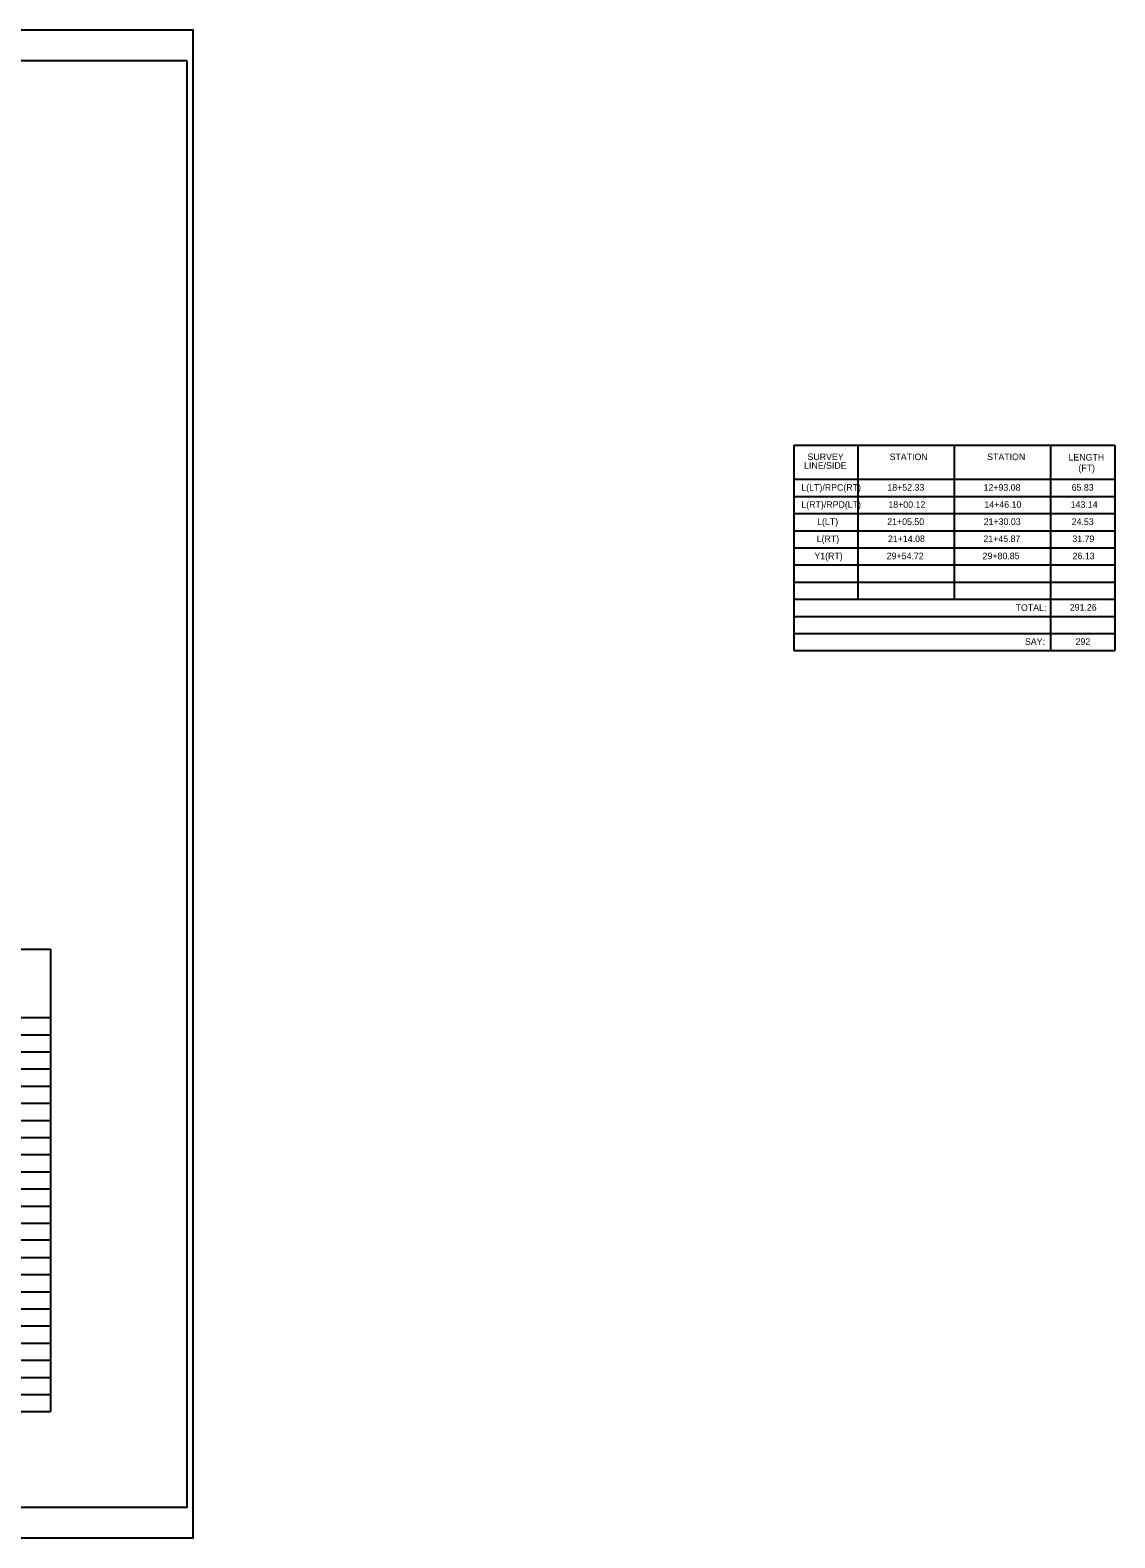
# Model space of a CAD drawing. Extents: x 2820318 to 2824860, y 680532 to 681838.
# Drawn here: x 2824069 to 2824860, y 680532 to 681632 of the extents above; entities that cross this region are included whole.
import ezdxf

# ---------------------------------------------------------------- set-up
doc = ezdxf.new("R2010")
doc.units = 0
for name, color, linetype in [('Default', 7, 'Continuous'), ('Sheet Cutting Line CELL', 7, 'Continuous'), ('Sheet Plot Border Inside CELL', 7, 'Continuous'), ('Sheet Plot Border Outside CELL', 7, 'Continuous'), ('Sheet Summary Combination CELL', 7, 'Continuous'), ('Sheet Summary Combination Grid CELL', 7, 'Continuous')]:
    doc.layers.add(name, color=color, linetype=linetype)

msp = doc.modelspace()

# ---------------------------------------------------------------- linework, layer by layer
at = {"layer": 'Default'}
msp.add_lwpolyline([(2822503.6, 681631.5), (2822503.6, 680531.5), (2824187.6, 680531.5), (2824187.6, 681631.5)], close=True, dxfattribs=at)
msp.add_lwpolyline([(2822503.6, 681631.5), (2822503.6, 680531.5), (2824187.6, 680531.5), (2824187.6, 681631.5)], close=True, dxfattribs=at)
at = {"layer": 'Sheet Cutting Line CELL'}
for p, q in [((2824187.6, 681631.5), (2822503.6, 681631.5)), ((2822503.6, 680531.5), (2824187.6, 680531.5))]:
    msp.add_line(p, q, dxfattribs=at)
at = {"layer": 'Sheet Plot Border Inside CELL'}
msp.add_lwpolyline([(2824183.1, 681609.1), (2822516.6, 681609.1), (2822516.6, 680554), (2824183.1, 680554)], close=True, dxfattribs=at)
at = {"layer": 'Sheet Plot Border Outside CELL'}
msp.add_lwpolyline([(2824187.6, 681631.5), (2822503.6, 681631.5), (2822503.6, 680531.5), (2824187.6, 680531.5)], close=True, dxfattribs=at)
at = {"layer": 'Sheet Summary Combination CELL'}
for p, q in [((2824767.1, 681328.8), (2824767.1, 681328.8)), ((2824773.4, 681328.7), (2824773.4, 681328.7)), ((2824782.4, 681328.9), (2824782.4, 681328.9)), ((2824788, 681328.8), (2824788, 681328.8))]:
    msp.add_line(p, q, dxfattribs=at)
at = {"layer": 'Sheet Summary Combination Grid CELL'}
for p, q in [((2824625.9, 681328.8), (2824860.3, 681328.8)), ((2824625.9, 681328.8), (2824625.9, 681178.8)), ((2824672.8, 681328.8), (2824672.8, 681216.3)), ((2824743.1, 681328.8), (2824743.1, 681216.3)), ((2824813.4, 681328.8), (2824813.4, 681178.8)), ((2824860.3, 681328.8), (2824860.3, 681178.8)), ((2824625.9, 681303.8), (2824860.3, 681303.8)), ((2824625.9, 681291.3), (2824860.3, 681291.3)), ((2824625.9, 681278.8), (2824860.3, 681278.8)), ((2824625.9, 681266.3), (2824860.3, 681266.3)), ((2824625.9, 681253.8), (2824860.3, 681253.8)), ((2824625.9, 681241.3), (2824860.3, 681241.3)), ((2824625.9, 681228.8), (2824860.3, 681228.8)), ((2824625.9, 681216.3), (2824860.3, 681216.3)), ((2824625.9, 681203.8), (2824860.3, 681203.8)), ((2824625.9, 681191.3), (2824860.3, 681191.3)), ((2824625.9, 681178.8), (2824860.3, 681178.8)), ((2822639.6, 680961.1), (2824083.4, 680961.1)), ((2824083.4, 680961.1), (2824083.4, 680711.1)), ((2822639.6, 680911.1), (2824083.4, 680911.1)), ((2822639.6, 680898.6), (2824083.4, 680898.6)), ((2822639.6, 680886.1), (2824083.4, 680886.1)), ((2822639.6, 680873.6), (2824083.4, 680873.6)), ((2822639.6, 680861.1), (2824083.4, 680861.1)), ((2822639.6, 680848.6), (2824083.4, 680848.6)), ((2822639.6, 680836.1), (2824083.4, 680836.1)), ((2822639.6, 680823.6), (2824083.4, 680823.6)), ((2822639.6, 680811.1), (2824083.4, 680811.1)), ((2822639.6, 680798.6), (2824083.4, 680798.6)), ((2822639.6, 680786.1), (2824083.4, 680786.1)), ((2822639.6, 680773.6), (2824083.4, 680773.6)), ((2822639.6, 680761.1), (2824083.4, 680761.1)), ((2822639.6, 680749), (2824083.4, 680749)), ((2822639.6, 680736.1), (2824083.4, 680736.1)), ((2822639.6, 680723.6), (2824083.4, 680723.6)), ((2822639.6, 680711.1), (2824083.4, 680711.1)), ((2824083.4, 680711.1), (2824083.4, 680623.6)), ((2822639.6, 680698.6), (2824083.4, 680698.6)), ((2822639.6, 680686.1), (2824083.4, 680686.1)), ((2822639.6, 680673.6), (2824083.4, 680673.6)), ((2822639.6, 680661.1), (2824083.4, 680661.1)), ((2822639.6, 680648.6), (2824083.4, 680648.6)), ((2822639.6, 680636.1), (2824083.4, 680636.1)), ((2822639.6, 680623.6), (2824083.4, 680623.6))]:
    msp.add_line(p, q, dxfattribs=at)

# ---------------------------------------------------------------- texts
at = {"layer": 'Sheet Summary Combination CELL'}
for s, p in [('SURVEY', (2824636, 681317.8)), ('STATION', (2824695.9, 681317.8)), ('STATION', (2824767.1, 681317.8)), ('LENGTH', (2824826.5, 681317.5)), ('LINE/SIDE', (2824633.5, 681311.5)), ('(FT)', (2824833.7, 681309.7)), ('L(LT)/RPC(RT)', (2824631.5, 681295.5)), ('18+52.33', (2824694.3, 681295.5)), ('12+93.08', (2824764.5, 681295.5)), ('65.83', (2824828.8, 681295.5)), ('L(RT)/RPD(LT)', (2824631.5, 681283)), ('18+00.12', (2824695, 681283)), ('14+46.10', (2824765.1, 681283)), ('143.14', (2824828.1, 681283)), ('L(LT)', (2824643, 681270.5)), ('21+05.50', (2824694.2, 681270.5)), ('21+30.03', (2824764.6, 681270.5)), ('24.53', (2824828.8, 681270.5)), ('L(RT)', (2824642.7, 681258)), ('21+14.08', (2824694.7, 681258)), ('21+45.87', (2824764.4, 681258)), ('31.79', (2824829.3, 681258)), ('Y1(RT)', (2824641, 681245.5)), ('29+54.72', (2824693.8, 681245.5)), ('29+80.85', (2824763.8, 681245.5)), ('26.13', (2824829.5, 681245.5)), ('TOTAL:', (2824787.9, 681207.8)), ('291.26', (2824827.4, 681208)), ('SAY:', (2824794.7, 681183)), ('292', (2824831.7, 681183))]:
    msp.add_text(s, height=4.8, dxfattribs=at).set_placement(p)

doc.saveas('drawing.dxf')
